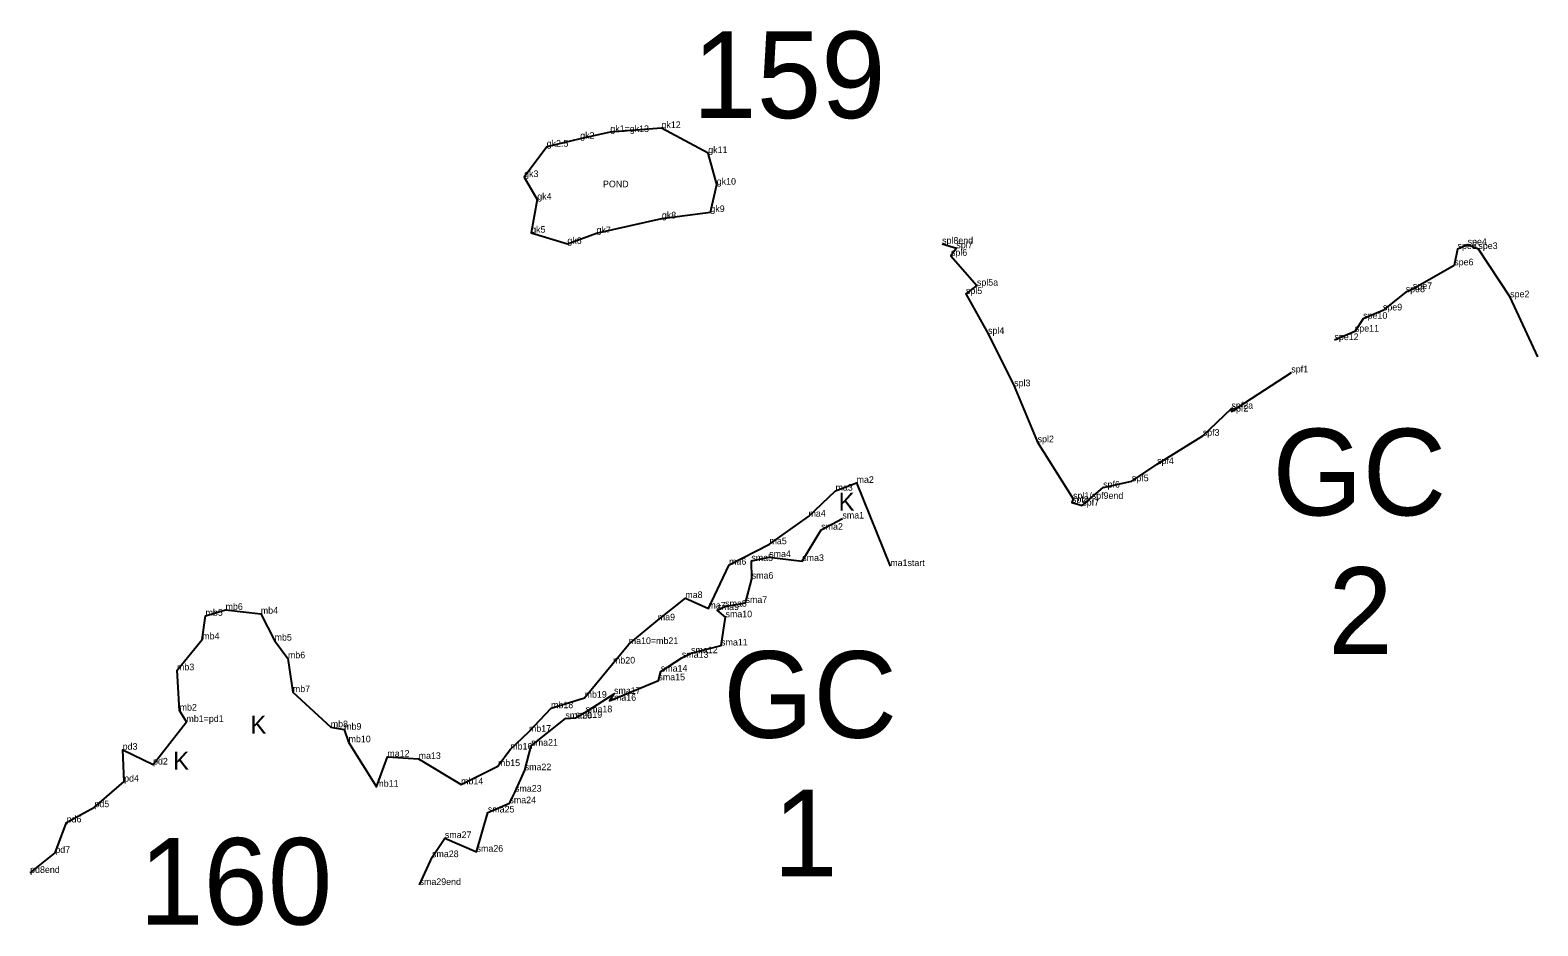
# Model space of a CAD drawing. Extents: x 2072529 to 2268796, y 436423 to 470397.
# Drawn here: x 2181788 to 2182926, y 451820 to 452495 of the extents above; entities that cross this region are included whole.
import ezdxf

# ---------------------------------------------------------------- set-up
doc = ezdxf.new("R2010")
doc.units = 0
for name, color, linetype in [('Default', 7, 'Continuous'), ('Exist Environmental Wetland Boundary', 7, 'Continuous'), ('Exist Environmental Wetland Boundary Cogo Comment', 7, 'Continuous'), ('Exist Environmental Wetland Boundary Cogo Point CELL', 7, 'Continuous'), ('Exist Hydro Jurisdictional Stream or Body of Water NEU Mitigable', 7, 'Continuous'), ('Exist Hydro Jurisdictional Stream or Body of Water NEU Mitigable Cogo Comment', 7, 'Continuous'), ('Exist Hydro Swamp or Marsh', 7, 'Continuous')]:
    doc.layers.add(name, color=color, linetype=linetype)

msp = doc.modelspace()

# ---------------------------------------------------------------- linework, layer by layer
at = {"layer": 'Exist Environmental Wetland Boundary'}
msp.add_lwpolyline([(2181788.2, 451859.5), (2181807.2, 451874.6), (2181815.7, 451897.6), (2181836.7, 451909.1), (2181859.1, 451928.4), (2181858, 451952.4), (2181880.9, 451941.3), (2181906.1, 451973.4), (2181901, 451982), (2181899, 452012.4), (2181918, 452035.7), (2181920.5, 452053.5), (2181935.6, 452058), (2181962.2, 452055.1), (2181972.6, 452034.8), (2181982.7, 452021.4), (2181986.4, 451995.9), (2182015, 451969.4), (2182025.1, 451967.6), (2182028.4, 451958.1), (2182049.4, 451924.5), (2182057.7, 451947.2), (2182081.3, 451945.5), (2182113.3, 451926.3), (2182141.1, 451940.1), (2182150.4, 451952.6), (2182164.5, 451966), (2182181.2, 451983.8), (2182206.5, 451991.7), (2182227.9, 452017.5), (2182239.8, 452032.2), (2182261.7, 452050.1), (2182282.5, 452066.9), (2182299.9, 452059), (2182315.5, 452092), (2182346, 452107.5), (2182375.4, 452128.3), (2182395.8, 452147.9), (2182411.7, 452153.8), (2182437.1, 452091)], dxfattribs=at)
at = {"layer": 'Exist Environmental Wetland Boundary Cogo Point CELL'}
for p, q in [((2182225.9, 452418.5), (2182225.9, 452418.5)), ((2182264.5, 452421.5), (2182264.5, 452421.5)), ((2182177.9, 452407.4), (2182177.9, 452407.4)), ((2182203.2, 452413.4), (2182203.2, 452413.4)), ((2182299.8, 452402.6), (2182299.8, 452402.6)), ((2182160.9, 452384.5), (2182160.9, 452384.5)), ((2182306.2, 452378.8), (2182306.2, 452378.8)), ((2182170.8, 452367.5), (2182170.8, 452367.5)), ((2182264.8, 452353.3), (2182264.8, 452353.3)), ((2182301.4, 452358.1), (2182301.4, 452358.1)), ((2182166.2, 452342.5), (2182166.2, 452342.5)), ((2182215.5, 452342.2), (2182215.5, 452342.2)), ((2182193.5, 452334.1), (2182193.5, 452334.1)), ((2182476.2, 452334.2), (2182476.2, 452334.2)), ((2182482.9, 452325.1), (2182482.9, 452325.1)), ((2182487, 452330.8), (2182487, 452330.8)), ((2182865.1, 452330.2), (2182865.1, 452330.2)), ((2182872.7, 452333.3), (2182872.7, 452333.3)), ((2182880.8, 452330.2), (2182880.8, 452330.2)), ((2182862.6, 452317.9), (2182862.6, 452317.9)), ((2182502.5, 452302.6), (2182502.5, 452302.6)), ((2182494.2, 452296.3), (2182494.2, 452296.3)), ((2182826, 452297.6), (2182826, 452297.6)), ((2182831.4, 452300), (2182831.4, 452300)), ((2182904.8, 452293.8), (2182904.8, 452293.8)), ((2182808.8, 452283.9), (2182808.8, 452283.9)), ((2182787.6, 452267.9), (2182787.6, 452267.9)), ((2182793.9, 452277.6), (2182793.9, 452277.6)), ((2182510.9, 452266.2), (2182510.9, 452266.2)), ((2182772.2, 452261.5), (2182772.2, 452261.5)), ((2182925.7, 452248.8), (2182925.7, 452248.8)), ((2182739.7, 452237.1), (2182739.7, 452237.1)), ((2182530.6, 452226.7), (2182530.6, 452226.7)), ((2182694.5, 452209.8), (2182694.5, 452209.8)), ((2182694.6, 452207.6), (2182694.6, 452207.6)), ((2182672.9, 452189.3), (2182672.9, 452189.3)), ((2182548.3, 452184.4), (2182548.3, 452184.4)), ((2182638.4, 452168), (2182638.4, 452168)), ((2182411.7, 452153.8), (2182411.7, 452153.8)), ((2182619.4, 452155), (2182619.4, 452155)), ((2182395.8, 452147.9), (2182395.8, 452147.9)), ((2182597.7, 452150.2), (2182597.7, 452150.2)), ((2182574.2, 452138.9), (2182574.2, 452138.9)), ((2182575, 452141.7), (2182575, 452141.7)), ((2182582, 452136.6), (2182582, 452136.6)), ((2182375.4, 452128.3), (2182375.4, 452128.3)), ((2182401, 452126.9), (2182401, 452126.9)), ((2182385, 452118.4), (2182385, 452118.4)), ((2182345.8, 452097.8), (2182345.8, 452097.8)), ((2182346, 452107.5), (2182346, 452107.5)), ((2182315.5, 452092), (2182315.5, 452092)), ((2182332.3, 452094.9), (2182332.3, 452094.9)), ((2182370.7, 452094.8), (2182370.7, 452094.8)), ((2182437.1, 452091), (2182437.1, 452091)), ((2182332.6, 452081.5), (2182332.6, 452081.5)), ((2182282.5, 452066.9), (2182282.5, 452066.9)), ((2182327.9, 452063.2), (2182327.9, 452063.2)), ((2181920.5, 452053.5), (2181920.5, 452053.5)), ((2181935.6, 452058), (2181935.6, 452058)), ((2181962.2, 452055.1), (2181962.2, 452055.1)), ((2182299.9, 452059), (2182299.9, 452059)), ((2182306.6, 452057.8), (2182306.6, 452057.8)), ((2182312.5, 452060.4), (2182312.5, 452060.4)), ((2182312.8, 452052.4), (2182312.8, 452052.4)), ((2182261.7, 452050.1), (2182261.7, 452050.1)), ((2181918, 452035.7), (2181918, 452035.7)), ((2181972.6, 452034.8), (2181972.6, 452034.8)), ((2182239.8, 452032.2), (2182239.8, 452032.2)), ((2182309.5, 452031.1), (2182309.5, 452031.1)), ((2181982.7, 452021.4), (2181982.7, 452021.4)), ((2182227.9, 452017.5), (2182227.9, 452017.5)), ((2182279.9, 452021.8), (2182279.9, 452021.8)), ((2182286.8, 452025.3), (2182286.8, 452025.3)), ((2181899, 452012.4), (2181899, 452012.4)), ((2182264, 452011.4), (2182264, 452011.4)), ((2181986.4, 451995.9), (2181986.4, 451995.9)), ((2182228.7, 451994.6), (2182228.7, 451994.6)), ((2182262.2, 452004.8), (2182262.2, 452004.8)), ((2182181.2, 451983.8), (2182181.2, 451983.8)), ((2182206.5, 451991.7), (2182206.5, 451991.7)), ((2182225.3, 451989.4), (2182225.3, 451989.4)), ((2181901, 451982), (2181901, 451982)), ((2181906.1, 451973.4), (2181906.1, 451973.4)), ((2182192, 451976), (2182192, 451976)), ((2182199.7, 451976.5), (2182199.7, 451976.5)), ((2182207.3, 451980.7), (2182207.3, 451980.7)), ((2182015, 451969.4), (2182015, 451969.4)), ((2182025.1, 451967.6), (2182025.1, 451967.6)), ((2182164.5, 451966), (2182164.5, 451966)), ((2181858, 451952.4), (2181858, 451952.4)), ((2182028.4, 451958.1), (2182028.4, 451958.1)), ((2182150.4, 451952.6), (2182150.4, 451952.6)), ((2182166.3, 451955.5), (2182166.3, 451955.5)), ((2181880.9, 451941.3), (2181880.9, 451941.3)), ((2182057.7, 451947.2), (2182057.7, 451947.2)), ((2182081.3, 451945.5), (2182081.3, 451945.5)), ((2182141.1, 451940.1), (2182141.1, 451940.1)), ((2181859.1, 451928.4), (2181859.1, 451928.4)), ((2182113.3, 451926.3), (2182113.3, 451926.3)), ((2182161.3, 451937), (2182161.3, 451937)), ((2182049.4, 451924.5), (2182049.4, 451924.5)), ((2182154, 451920.8), (2182154, 451920.8)), ((2181836.7, 451909.1), (2181836.7, 451909.1)), ((2182133.5, 451905.1), (2182133.5, 451905.1)), ((2182149.8, 451912.1), (2182149.8, 451912.1)), ((2181815.7, 451897.6), (2181815.7, 451897.6)), ((2182101.1, 451885.8), (2182101.1, 451885.8)), ((2181807.2, 451874.6), (2181807.2, 451874.6)), ((2182091.4, 451871.4), (2182091.4, 451871.4)), ((2182125, 451875.5), (2182125, 451875.5)), ((2181788.2, 451859.5), (2181788.2, 451859.5)), ((2182082, 451850.4), (2182082, 451850.4))]:
    msp.add_line(p, q, dxfattribs=at)
at = {"layer": 'Exist Hydro Jurisdictional Stream or Body of Water NEU Mitigable'}
msp.add_lwpolyline([(2182225.9, 452418.5), (2182203.2, 452413.4), (2182177.9, 452407.4), (2182160.9, 452384.5), (2182170.8, 452367.5), (2182166.2, 452342.5), (2182193.5, 452334.1), (2182215.5, 452342.2), (2182264.8, 452353.3), (2182301.4, 452358.1), (2182306.2, 452378.8), (2182299.8, 452402.6), (2182264.5, 452421.5)], close=True, dxfattribs=at)
for points in [[(2182476.2, 452334.2), (2182487, 452330.8), (2182482.9, 452325.1), (2182502.5, 452302.6), (2182494.2, 452296.3), (2182510.9, 452266.2), (2182530.6, 452226.7), (2182548.3, 452184.4), (2182575, 452141.7)], [(2182925.7, 452248.8), (2182904.8, 452293.8), (2182880.8, 452330.2), (2182872.7, 452333.3), (2182865.1, 452330.2), (2182862.6, 452317.9), (2182831.4, 452300), (2182826, 452297.6), (2182808.8, 452283.9), (2182793.9, 452277.6), (2182787.6, 452267.9), (2182772.2, 452261.5)], [(2182575, 452141.7), (2182574.2, 452138.9), (2182582, 452136.6), (2182597.7, 452150.2), (2182619.4, 452155), (2182638.4, 452168), (2182672.9, 452189.3), (2182694.5, 452209.8), (2182694.6, 452207.6), (2182739.7, 452237.1)], [(2182082, 451850.4), (2182091.4, 451871.4), (2182101.1, 451885.8), (2182125, 451875.5), (2182133.5, 451905.1), (2182149.8, 451912.1), (2182154, 451920.8), (2182161.3, 451937), (2182166.3, 451955.5), (2182192, 451976), (2182199.7, 451976.5), (2182207.3, 451980.7), (2182228.7, 451994.6), (2182225.3, 451989.4), (2182262.2, 452004.8), (2182264, 452011.4), (2182279.9, 452021.8), (2182286.8, 452025.3), (2182309.5, 452031.1), (2182312.8, 452052.4), (2182306.6, 452057.8), (2182312.5, 452060.4), (2182327.9, 452063.2), (2182332.6, 452081.5), (2182332.3, 452094.9), (2182345.8, 452097.8), (2182370.7, 452094.8), (2182385, 452118.4), (2182401, 452126.9)]]:
    msp.add_lwpolyline(points, dxfattribs=at)

# ---------------------------------------------------------------- texts
at = {"layer": 'Default'}
for s, height, p in [('159', 65.34, (2182287.8, 452429)), ('GC', 65.34, (2182725.5, 452129.3)), ('2', 65.3, (2182767.6, 452024.8)), ('GC', 65.34, (2182311.1, 451961.5)), ('1', 65.3, (2182348.8, 451857)), ('160', 65.34, (2181870.4, 451820.5))]:
    msp.add_text(s, height=height, dxfattribs=at).set_placement(p)
at = {"layer": 'Exist Environmental Wetland Boundary Cogo Comment'}
for s, p in [('ma2', (2182411.7, 452153.8)), ('ma3', (2182395.8, 452147.9)), ('ma4', (2182375.4, 452128.3)), ('ma5', (2182346, 452107.5)), ('ma6', (2182315.5, 452092)), ('ma1start', (2182437.1, 452091)), ('mb6', (2181935.6, 452058)), ('ma8', (2182282.5, 452066.9)), ('ma7', (2182299.9, 452059)), ('mb5', (2181920.5, 452053.5)), ('mb4', (2181962.2, 452055.1)), ('ma9', (2182261.7, 452050.1)), ('mb4', (2181918, 452035.7)), ('mb5', (2181972.6, 452034.8)), ('ma10=mb21', (2182239.8, 452032.2)), ('mb3', (2181899, 452012.4)), ('mb6', (2181982.7, 452021.4)), ('mb20', (2182227.9, 452017.5)), ('mb7', (2181986.4, 451995.9)), ('mb19', (2182206.5, 451991.7)), ('mb2', (2181901, 451982)), ('mb18', (2182181.2, 451983.8)), ('mb1=pd1', (2181906.1, 451973.4)), ('mb8', (2182015, 451969.4)), ('mb9', (2182025.1, 451967.6)), ('mb10', (2182028.4, 451958.1)), ('mb17', (2182164.5, 451966)), ('pd3', (2181858, 451952.4)), ('ma12', (2182057.7, 451947.2)), ('ma13', (2182081.3, 451945.5)), ('mb16', (2182150.4, 451952.6)), ('pd2', (2181880.9, 451941.3)), ('mb15', (2182141.1, 451940.1)), ('pd4', (2181859.1, 451928.4)), ('mb11', (2182049.4, 451924.5)), ('mb14', (2182113.3, 451926.3)), ('pd5', (2181836.7, 451909.1)), ('pd6', (2181815.7, 451897.6)), ('pd7', (2181807.2, 451874.6)), ('pd8end', (2181788.2, 451859.5))]:
    msp.add_text(s, height=5, dxfattribs=at).set_placement(p)
at = {"layer": 'Exist Hydro Jurisdictional Stream or Body of Water NEU Mitigable Cogo Comment'}
for s, p in [('gk12', (2182264.5, 452421.5)), ('gk2', (2182203.2, 452413.4)), ('gk1=gk13', (2182225.9, 452418.5)), ('gk2.5', (2182177.9, 452407.4)), ('gk11', (2182299.8, 452402.6)), ('gk3', (2182160.9, 452384.5)), ('POND', (2182220.4, 452376.8)), ('gk10', (2182306.2, 452378.8)), ('gk4', (2182170.8, 452367.5)), ('gk8', (2182264.8, 452353.3)), ('gk9', (2182301.4, 452358.1)), ('gk5', (2182166.2, 452342.5)), ('gk7', (2182215.5, 452342.2)), ('gk6', (2182193.5, 452334.1)), ('spl8end', (2182476.2, 452334.2)), ('spl7', (2182487, 452330.8)), ('spe4', (2182872.7, 452333.3)), ('spl6', (2182482.9, 452325.1)), ('spe5', (2182865.1, 452330.2)), ('spe3', (2182880.8, 452330.2)), ('spe6', (2182862.6, 452317.9)), ('spl5a', (2182502.5, 452302.6)), ('spe8', (2182826, 452297.6)), ('spe7', (2182831.4, 452300)), ('spl5', (2182494.2, 452296.3)), ('spe2', (2182904.8, 452293.8)), ('spe10', (2182793.9, 452277.6)), ('spe9', (2182808.8, 452283.9)), ('spl4', (2182510.9, 452266.2)), ('spe11', (2182787.6, 452267.9)), ('spe12', (2182772.2, 452261.5)), ('spf1', (2182739.7, 452237.1)), ('spl3', (2182530.6, 452226.7)), ('spf2a', (2182694.5, 452209.8)), ('spf2', (2182694.6, 452207.6)), ('spl2', (2182548.3, 452184.4)), ('spf3', (2182672.9, 452189.3)), ('spf4', (2182638.4, 452168)), ('spf6', (2182597.7, 452150.2)), ('spf5', (2182619.4, 452155)), ('spf8', (2182574.2, 452138.9)), ('spl1/spf9end', (2182575, 452141.7)), ('sma1', (2182401, 452126.9)), ('spf7', (2182582, 452136.6)), ('sma2', (2182385, 452118.4)), ('sma5', (2182332.3, 452094.9)), ('sma4', (2182345.8, 452097.8)), ('sma3', (2182370.7, 452094.8)), ('sma6', (2182332.6, 452081.5)), ('sma9', (2182306.6, 452057.8)), ('sma8', (2182312.5, 452060.4)), ('sma7', (2182327.9, 452063.2)), ('sma10', (2182312.8, 452052.4)), ('sma12', (2182286.8, 452025.3)), ('sma11', (2182309.5, 452031.1)), ('sma13', (2182279.9, 452021.8)), ('sma15', (2182262.2, 452004.8)), ('sma14', (2182264, 452011.4)), ('sma16', (2182225.3, 451989.4)), ('sma17', (2182228.7, 451994.6)), ('sma18', (2182207.3, 451980.7)), ('sma20', (2182192, 451976)), ('sma19', (2182199.7, 451976.5)), ('sma21', (2182166.3, 451955.5)), ('sma22', (2182161.3, 451937)), ('sma24', (2182149.8, 451912.1)), ('sma23', (2182154, 451920.8)), ('sma25', (2182133.5, 451905.1)), ('sma27', (2182101.1, 451885.8)), ('sma28', (2182091.4, 451871.4)), ('sma26', (2182125, 451875.5)), ('sma29end', (2182082, 451850.4))]:
    msp.add_text(s, height=5, dxfattribs=at).set_placement(p)
at = {"layer": 'Exist Hydro Swamp or Marsh'}
for p in [(2182398.1, 452132.7), (2181954.3, 451964.6), (2181896, 451937.3)]:
    msp.add_text('K', height=13.6, dxfattribs=at).set_placement(p)

doc.saveas('drawing.dxf')
